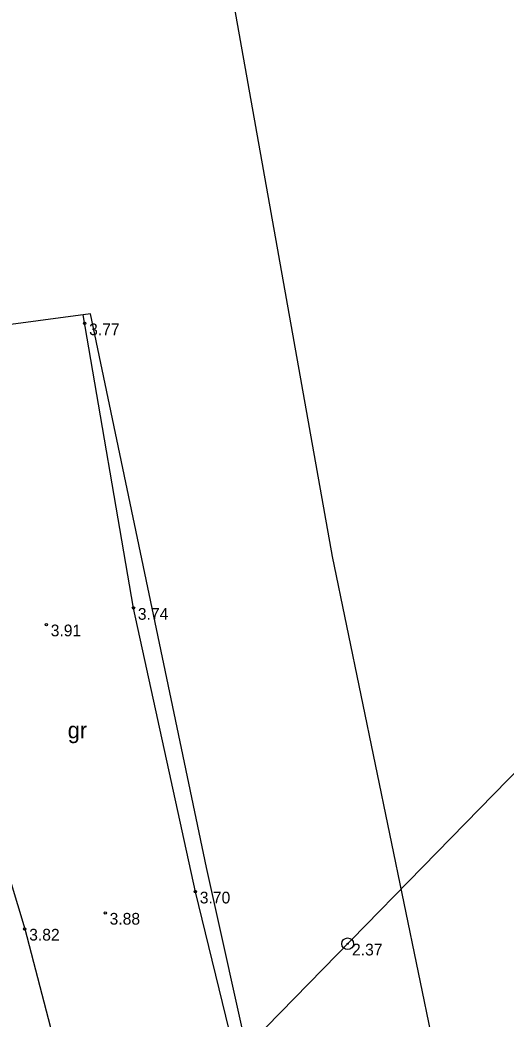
# Model space of a CAD drawing. Extents: x 321079 to 321220, y 257030 to 257220.
# Drawn here: x 321169.55 to 321190.3, y 257130.98 to 257173.58 of the extents above; entities that cross this region are included whole.
import ezdxf

# ---------------------------------------------------------------- set-up
doc = ezdxf.new("R2010")
doc.units = 0
for name, color, linetype in [('CELI_CMAL_####_####_#', 7, 'Continuous'), ('CELI_CSEG_####_TKST_#', 7, 'Continuous'), ('ELEK_ELEM_####_####_#', 7, 'Continuous'), ('ELEK_VADV_ZSPR_####_#', 7, 'Continuous'), ('RAMI_UZMR_####_####_#', 7, 'Continuous'), ('RELJ_AATZ_####_TKST_#', 7, 'Continuous'), ('RELJ_ELEM_####_####_#', 7, 'Continuous'), ('ROBZ_UZMR_####_####_#', 7, 'Continuous')]:
    doc.layers.add(name, color=color, linetype=linetype)

msp = doc.modelspace()

# ---------------------------------------------------------------- linework, layer by layer
at = {"layer": 'CELI_CMAL_####_####_#'}
for points in [[(321182.971, 257111.303), (321180.196, 257123.466), (321177.038, 257136.408), (321174.394, 257148.502), (321172.25, 257161.008)], [(321164.229, 257149.382), (321166.166, 257146.657), (321169.755, 257134.824), (321173.111, 257121.931), (321175.798, 257109.619)]]:
    msp.add_lwpolyline(points, dxfattribs=at)
at = {"layer": 'ELEK_ELEM_####_####_#'}
for radius in [0.25, 0.0225]:
    msp.add_circle((321183.536, 257134.189), radius, dxfattribs=at)
at = {"layer": 'ELEK_VADV_ZSPR_####_#'}
msp.add_line((321190.982, 257141.796), (321156.234, 257106.297), dxfattribs=at)
at = {"layer": 'RAMI_UZMR_####_####_#'}
msp.add_lwpolyline([(321107.5, 257141.5), (321108.611, 257133.395), (321131.584, 257099.382), (321150.327, 257105.322), (321177.121, 257109.842), (321183.308, 257111.386), (321177.517, 257137.442), (321172.561, 257161.05), (321156.27, 257158.872), (321156.852, 257154.517), (321139.352, 257150.329), (321114.57, 257145.337)], close=True, dxfattribs=at)
at = {"layer": 'RELJ_ELEM_####_####_#'}
for centre in [(321172.314, 257160.635), (321174.394, 257148.502), (321170.674, 257147.797), (321177.038, 257136.408), (321173.188, 257135.504), (321169.755, 257134.824)]:
    msp.add_circle(centre, 0.05, dxfattribs=at)
at = {"layer": 'ROBZ_UZMR_####_####_#'}
for p, q in [((321182.887, 257150.703), (321175.886, 257189.92)), ((321194.114, 257096.554), (321182.887, 257150.703))]:
    msp.add_line(p, q, dxfattribs=at)

# ---------------------------------------------------------------- texts
at = {"layer": 'CELI_CSEG_####_TKST_#'}
msp.add_text('gr', height=0.7, dxfattribs=at).set_placement((321171.585, 257142.946))
at = {"layer": 'RELJ_AATZ_####_TKST_#'}
for s, p in [(' 3.77', (321172.314, 257160.135)), (' 3.74', (321174.394, 257148.002)), (' 3.91', (321170.674, 257147.297)), (' 3.70', (321177.038, 257135.908)), (' 3.88', (321173.188, 257135.004)), (' 3.82', (321169.755, 257134.324)), (' 2.37', (321183.536, 257133.689))]:
    msp.add_text(s, height=0.5, dxfattribs=at).set_placement(p)

doc.saveas('drawing.dxf')
